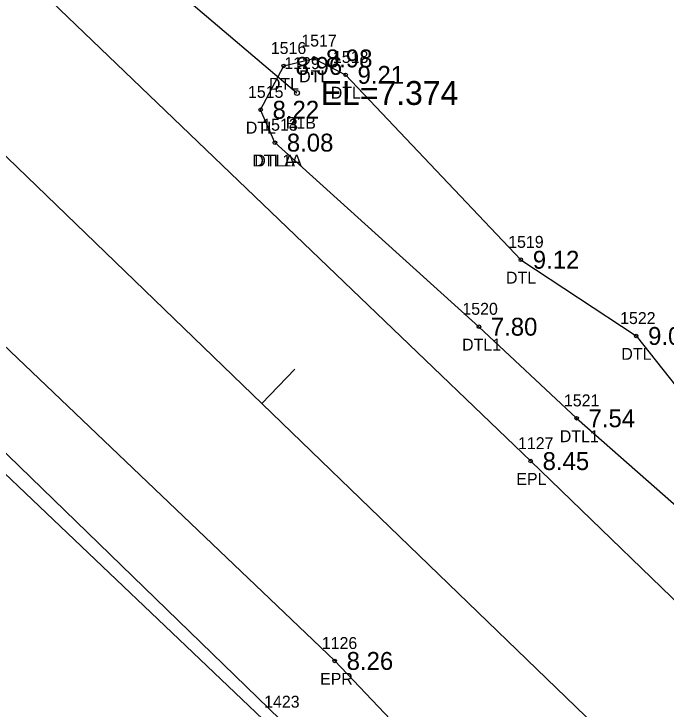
# Model space of a CAD drawing. Extents: x 2608598 to 2610682, y 641451 to 643526.
# Drawn here: x 2608999.2 to 2609053.8, y 643150.2 to 643208.4 of the extents above; entities that cross this region are included whole.
import ezdxf

# ---------------------------------------------------------------- set-up
doc = ezdxf.new("R2010")
doc.units = 0
for name, color, linetype in [('RD_EX_DR_Pipe', 7, 'Continuous'), ('RD_EX_DR_Pipe_txCode', 7, 'Continuous'), ('RD_EX_Fence_Other', 7, 'Continuous'), ('RD_EX_Fence_Other_txCode', 7, 'Continuous'), ('RD_EX_H2O', 7, 'Continuous'), ('RD_EX_H2O_txCode', 7, 'Continuous'), ('RD_EX_Road', 7, 'Continuous'), ('RD_EX_Road_txCode', 7, 'Continuous'), ('RD_EX_TX_H2O_ELEV', 7, 'Continuous'), ('RD_EX_TX_Road_ELEV', 7, 'Continuous'), ('RD_HC_Cl', 7, 'Continuous'), ('RD_HC_Data_Tic', 7, 'Continuous'), ('RD_SMD_Locator', 7, 'Continuous'), ('RD_TX_Pipe_ElevEX', 7, 'Continuous')]:
    doc.layers.add(name, color=color, linetype=linetype)

msp = doc.modelspace()

# ---------------------------------------------------------------- linework, layer by layer
at = {"layer": 'RD_EX_DR_Pipe'}
for p, q in [((2608897.517, 643265.845), (2609033.537, 643136.49)), ((2609009.261, 643213.385), (2609022.901, 643201.792))]:
    msp.add_line(p, q, dxfattribs=at)
at = {"layer": 'RD_EX_Fence_Other'}
msp.add_lwpolyline([(2608929.733, 643236.719), (2608949.247, 643219.372), (2609021.489, 643149.273), (2609029.568, 643141.046), (2609030.561, 643134.386), (2609028.416, 643127.37), (2609017.458, 643118.156)], dxfattribs=at)
at = {"layer": 'RD_EX_H2O'}
for points in [[(2609021.05, 643197.631), (2609019.853, 643200.385), (2609021.789, 643204.059), (2609024.325, 643204.687), (2609026.977, 643203.311), (2609041.67, 643187.813), (2609051.338, 643181.427), (2609055.817, 643175.793), (2609056.795, 643174.291), (2609059.172, 643170.113), (2609061.344, 643168.412), (2609069.658, 643161.399)], [(2609021.05, 643197.631), (2609038.152, 643182.202), (2609046.346, 643174.525), (2609056.569, 643165.532), (2609065.72, 643157.084), (2609069.087, 643156.599), (2609071.239, 643158.958), (2609069.658, 643161.399)]]:
    msp.add_lwpolyline(points, dxfattribs=at)
at = {"layer": 'RD_EX_Road'}
for points in [[(2608823.565, 643381.898), (2608829.584, 643376.805), (2608846.192, 643359.903), (2608852.068, 643354.1), (2608873.124, 643334.611), (2608877.912, 643330.135), (2608897.264, 643311.51), (2608898.769, 643309.298), (2608970.3, 643240.177), (2609042.495, 643170.94), (2609058.512, 643155.458)], [(2608806.889, 643364.989), (2608810.184, 643361.1), (2608820.754, 643351.249), (2608881.81, 643292.235), (2608917.833, 643257.495), (2608933.208, 643242.709), (2608954.068, 643222.833), (2609026.064, 643154.189), (2609039.601, 643139.963), (2609073.879, 643106.954), (2609100.48, 643081.888), (2609124.194, 643058.866), (2609171.612, 643013.711), (2609183.195, 643002.284), (2609197.913, 642988.365), (2609247.586, 642940.954), (2609328.02, 642863.599), (2609402.609, 642790.299), (2609474.235, 642720.69), (2609483.838, 642711.579), (2609495.782, 642699.917), (2609509.808, 642686.45)]]:
    msp.add_lwpolyline(points, dxfattribs=at)
at = {"layer": 'RD_HC_Cl'}
msp.add_line((2608814.812, 643373.733), (2610092.394, 642140.787), dxfattribs=at)
at = {"layer": 'RD_HC_Data_Tic'}
msp.add_line((2609019.953, 643175.759), (2609022.73, 643178.638), dxfattribs=at)
at = {"layer": 'RD_SMD_Locator'}
for centre, radius in [((2609024.325, 643204.687), 0.15), ((2609021.789, 643204.059), 0.15), ((2609026.977, 643203.311), 0.15), ((2609022.901, 643201.792), 0.2), ((2609019.853, 643200.385), 0.15), ((2609021.05, 643197.631), 0.15), ((2609021.05, 643197.631), 0.15), ((2609041.67, 643187.813), 0.15), ((2609038.152, 643182.202), 0.15), ((2609051.338, 643181.427), 0.15), ((2609046.346, 643174.525), 0.15), ((2609042.495, 643170.94), 0.15), ((2609026.064, 643154.189), 0.15)]:
    msp.add_circle(centre, radius, dxfattribs=at)

# ---------------------------------------------------------------- texts
at = {"layer": 'RD_EX_DR_Pipe_txCode'}
for s, p in [('1129', (2609021.838, 643203.792)), ('P1B', (2609021.956, 643198.792))]:
    msp.add_text(s, height=1, dxfattribs=at).set_placement(p)
at = {"layer": 'RD_EX_Fence_Other_txCode'}
msp.add_text('1423', height=1, dxfattribs=at).set_placement((2609020.143, 643150.273))
at = {"layer": 'RD_EX_H2O_txCode'}
for s, p in [('1517', (2609023.262, 643205.687)), ('1516', (2609020.702, 643205.059)), ('1518', (2609025.914, 643204.311)), ('DTL', (2609023.08, 643202.687)), ('DTL', (2609020.545, 643202.059)), ('1515', (2609018.79, 643201.385)), ('DTL', (2609025.733, 643201.311)), ('1513', (2609019.987, 643198.631)), ('1514', (2609019.987, 643198.631)), ('DTL', (2609018.609, 643198.385)), ('DTL1A', (2609019.152, 643195.631)), ('DTLA', (2609019.318, 643195.631)), ('1519', (2609040.607, 643188.813)), ('DTL', (2609040.426, 643185.813)), ('1520', (2609036.766, 643183.202)), ('1522', (2609049.991, 643182.427)), ('DTL1', (2609036.742, 643180.202)), ('DTL', (2609050.094, 643179.427)), ('1521', (2609045.283, 643175.525)), ('DTL1', (2609044.936, 643172.525))]:
    msp.add_text(s, height=1, dxfattribs=at).set_placement(p)
at = {"layer": 'RD_EX_Road_txCode'}
for s, p in [('1127', (2609041.432, 643171.94)), ('EPL', (2609041.29, 643168.94)), ('1126', (2609024.977, 643155.189)), ('EPR', (2609024.836, 643152.189))]:
    msp.add_text(s, height=1, dxfattribs=at).set_placement(p)
at = {"layer": 'RD_EX_TX_H2O_ELEV'}
for s, p in [('8.98', (2609025.325, 643203.937)), ('8.96', (2609022.789, 643203.309)), ('9.21', (2609027.977, 643202.561)), ('8.22', (2609020.853, 643199.635)), ('8.08', (2609022.05, 643196.881)), ('8.08', (2609022.05, 643196.881)), ('9.12', (2609042.67, 643187.063)), ('7.80', (2609039.152, 643181.452)), ('9.04', (2609052.338, 643180.677)), ('7.54', (2609047.346, 643173.775))]:
    msp.add_text(s, height=1.5, dxfattribs=at).set_placement(p)
at = {"layer": 'RD_EX_TX_Road_ELEV'}
for s, p in [('8.45', (2609043.495, 643170.19)), ('8.26', (2609027.064, 643153.439))]:
    msp.add_text(s, height=1.5, dxfattribs=at).set_placement(p)
at = {"layer": 'RD_TX_Pipe_ElevEX'}
msp.add_text('EL=7.374', height=2, dxfattribs=at).set_placement((2609024.901, 643200.792))

doc.saveas('drawing.dxf')
